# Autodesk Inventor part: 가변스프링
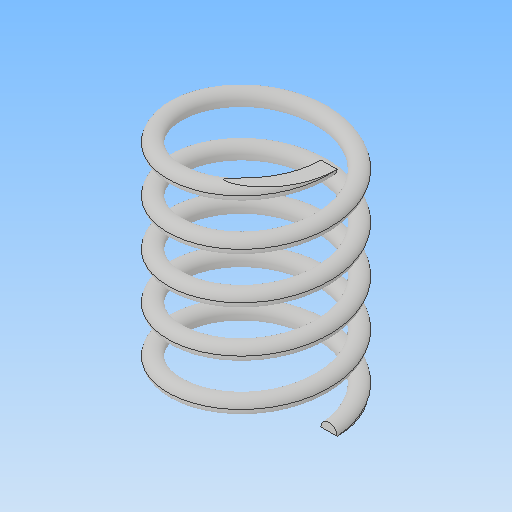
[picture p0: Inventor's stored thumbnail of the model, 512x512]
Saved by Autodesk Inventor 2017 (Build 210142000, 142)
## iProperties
Part Number: 가변스프링
Material: 일반
Document SubType Name: Modeling
Designer: MRC
Density: 1 g/cm^3
Appearance: 기본값
Mass: 0.874626 g
Surface Area: 17.7559 cm^2
Volume: 0.874626 cm^3
Author: MRC
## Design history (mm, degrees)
sketch "스케치1"
  geometry: L1 (0, 0)-(9, 0); L2 (0, 0)-(0, 28.5); L3 (0, 28.5)-(8, 28.5); C1 r 1 at (9, 0)
  constraints: 6 end point, 2 horizontal, 1 centre point, 1 coincident, 1 vertical
  dimensions: "d0" = 9 distance of L1.start L1.end; "d1" = 2 diameter of C1; "d2" = 28.5 distance of L1.start L2.end (derived)
feature "코일1" sketch "스케치1" pitch "d3" = 10; turns "d5" = 5; dims "d4" = 28.5 (= d2), "d6" = 0, angle "d7" = 90 deg, angle "d8" = 90 deg, "d9" = 0, "d10" = 0
sketch "스케치2"
  geometry: L1 (28.5, 16.5)-(0, 16.5); L2 (0, 16.5)-(0, -16.5); L3 (0, -16.5)-(28.5, -16.5); L4 (28.5, -16.5)-(28.5, 16.5); 2 further points
  constraints: 8 end point, 2 parallel, 1 coincident, 1 horizontal, 1 midpoint, 1 perpendicular
  dimensions: "d11" = 33 distance between parallel lines of L3 L1; "d12" = 28.5 distance between parallel lines of L2 L4 (= d2)
extrude "돌출1" sketch "스케치2" stored distance "d13" = 50; taper "d14" = 0 deg
node "솔리드1"
